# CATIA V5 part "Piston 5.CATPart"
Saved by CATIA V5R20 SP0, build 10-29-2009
Part number: Piston 5
Publications: "Plan.1"
Bounding box of the stored display mesh (mm): x -45.499 to 45.499, y 82.941 to 173.939, z 240.347 to 434.461
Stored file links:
  C:\Users\thinkmotion1\Desktop\Khaled_IAO_Pack2\IAO_2010_1412_jclement\Non_Optimise\Piston 5.CATPart
  C:\Users\thinkmotion1\Desktop\Khaled_IAO_Pack2\IAO_2010_1412_jclement\Non_Optimise\Synthese IAO_2.CATProduct
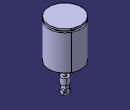
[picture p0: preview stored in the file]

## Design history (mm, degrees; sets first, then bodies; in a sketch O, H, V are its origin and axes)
Set1
  DatumCurve1: linked copy from another document
  DatumCurve2: linked copy from another document
  DatumSurface1: linked copy from another document
Set2
  Plane1: type Offset, RefPlane yz-plane, Offset 5, reversed
Body1 (main body)
  Sketch1 on Plane1, origin (-5, 0, 0), H (0, 1, 0), V (0, 0, 1)
    line L1 (120.9403, 268.9615) -> (135.9403, 268.9615)
    line L2 (135.9403, 268.9615) -> (135.9403, 256.9615)
    line L3 (120.9403, 256.9615) -> (120.9403, 268.9615)
    point P3 (135.9403, 256.9615)
    point P4 (120.9403, 256.9615)
    arc A1 centre (128.4403, 250.3471) radius 10 from (120.9403, 256.9615) to (135.9403, 256.9615) ccw
    reference projected circle E1 centre (128.4403, 250.3471) radius 6 from edge of DatumCurve1
    reference projected arc E2 centre (128.4403, 250.3471) radius 10 from (132.3423, 241.1398) to (120.6938, 244.0232) ccw from edge of DatumCurve2
    distance L2 L3 = 15
    distance P3 P4 V = 0
    length L3 = 12
    horizontal: L1 H
    vertical: L2 V, L3 V
    concentricity: E1 A1
    coincidence: A1 E2
  Pad1: profile Sketch1, direction (1, 0, 0), length 10
  Sketch2 on end face of Pad1, origin (5, 0, 0), H (0, 1, 0), V (0, 0, 1)
    circle A1 centre (128.4403, 250.3471) radius 6
    reference projected circle E1 centre (128.4403, 250.3471) radius 6 from edge of DatumCurve1
    coincidence: A1 E1
  Pad2: profile Sketch2, direction (1, 0, 0), up to face of DatumSurface1, opposite side length 15
  Sketch3 on yz-plane, origin (0, 0, 0), H (0, 1, 0), V (0, 0, 1)
    axis line L1 (128.4403, 332.7179) -> (128.4403, 216.6975)
    reference projected line E1 (120.9403, 268.9615) -> (120.9403, 256.9615) from edge [face of Pad1 from Sketch1.L3 | end face of Pad1]
    reference projected line E2 (135.9403, 256.9615) -> (135.9403, 268.9615) from edge [face of Pad1 from Sketch1.L2 | end face of Pad1]
    point P3 (128.4403, 434.4615)
    line L2 (128.4403, 434.4615) -> (82.9403, 434.4615)
    point P4 (82.9403, 434.4615)
    line L3 (82.9403, 434.4615) -> (82.9403, 429.4615)
    point P5 (82.9403, 324.4615)
    line L4 (82.9403, 324.4615) -> (117.4403, 324.4615)
    line L5 (117.4403, 324.4615) -> (117.4403, 318.9615)
    line L6 (117.4403, 318.9615) -> (122.4403, 318.9615)
    line L7 (122.4403, 318.9615) -> (122.4403, 313.9615)
    line L8 (122.4403, 313.9615) -> (115.4403, 313.9615)
    line L9 (115.4403, 313.9615) -> (115.4403, 305.9615)
    line L10 (115.4403, 305.9615) -> (123.4403, 305.9615)
    line L11 (123.4403, 305.9615) -> (123.4403, 286.9615)
    line L12 (123.4403, 286.9615) -> (117.4403, 286.9615)
    point P14 (117.4403, 286.9615)
    line L13 (117.4403, 286.9615) -> (117.4403, 268.9615)
    line L14 (117.4403, 268.9615) -> (128.4403, 268.9615)
    point P16 (128.4403, 268.9615)
    line L15 (128.4403, 268.9615) -> (128.4403, 434.4615)
    reference projected line E3 (158.9539, 268.9615) -> (143.9539, 268.9615) from edge [face of Pad1 from Sketch1.L1 | end face of Pad1]
    line L16 (82.9403, 429.4615) -> (87.9403, 429.4615)
    line L17 (87.9403, 429.4615) -> (87.9403, 424.4615)
    line L18 (87.9403, 424.4615) -> (82.9403, 424.4615)
    line L19 (82.9403, 424.4615) -> (82.9403, 324.4615)
    distance L13 L15 = 11
    length L12 = 6
    length L11 = 19
    length L9 = 8
    length L10 = 8
    length L13 = 18
    length L7 = 5
    length L6 = 5
    length L5 = 5.5
    length L4 = 34.5
    distance L16 L2 = 5
    length L18 = 5
    length L17 = 5
    distance P4 P5 = 110
    vertical: L1 V, L3 V, L5 V, L7 V, L9 V, L11 V, L13 V, L15 V, L17 V, L19 V
    symmetry: E1 E2 L1
    coincidence: P3 L1, P14 L5, P16 L1, L14 E3, L3 L19
    horizontal: L2 H, L4 H, L6 H, L8 H, L10 H, L12 H, L14 H, L16 H, L18 H
  Shaft1: profile Sketch3, axis Sketch3.L1, angle 360
  Sketch4 on face of Shaft1 from Sketch3.L2, origin (0, 0, 434.4615), H (1, 0, 0), V (0, 1, 0)
    point P1 (0, 128.4403)
    reference projected circle E1 centre (0, 128.4403) radius 45.5 from edge [face of Shaft1 from Sketch3.L2 | face of Shaft1 from Sketch3.L3]
    coincidence: P1 V
    concentricity: P1 E1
